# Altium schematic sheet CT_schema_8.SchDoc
size 278 x 170 mm
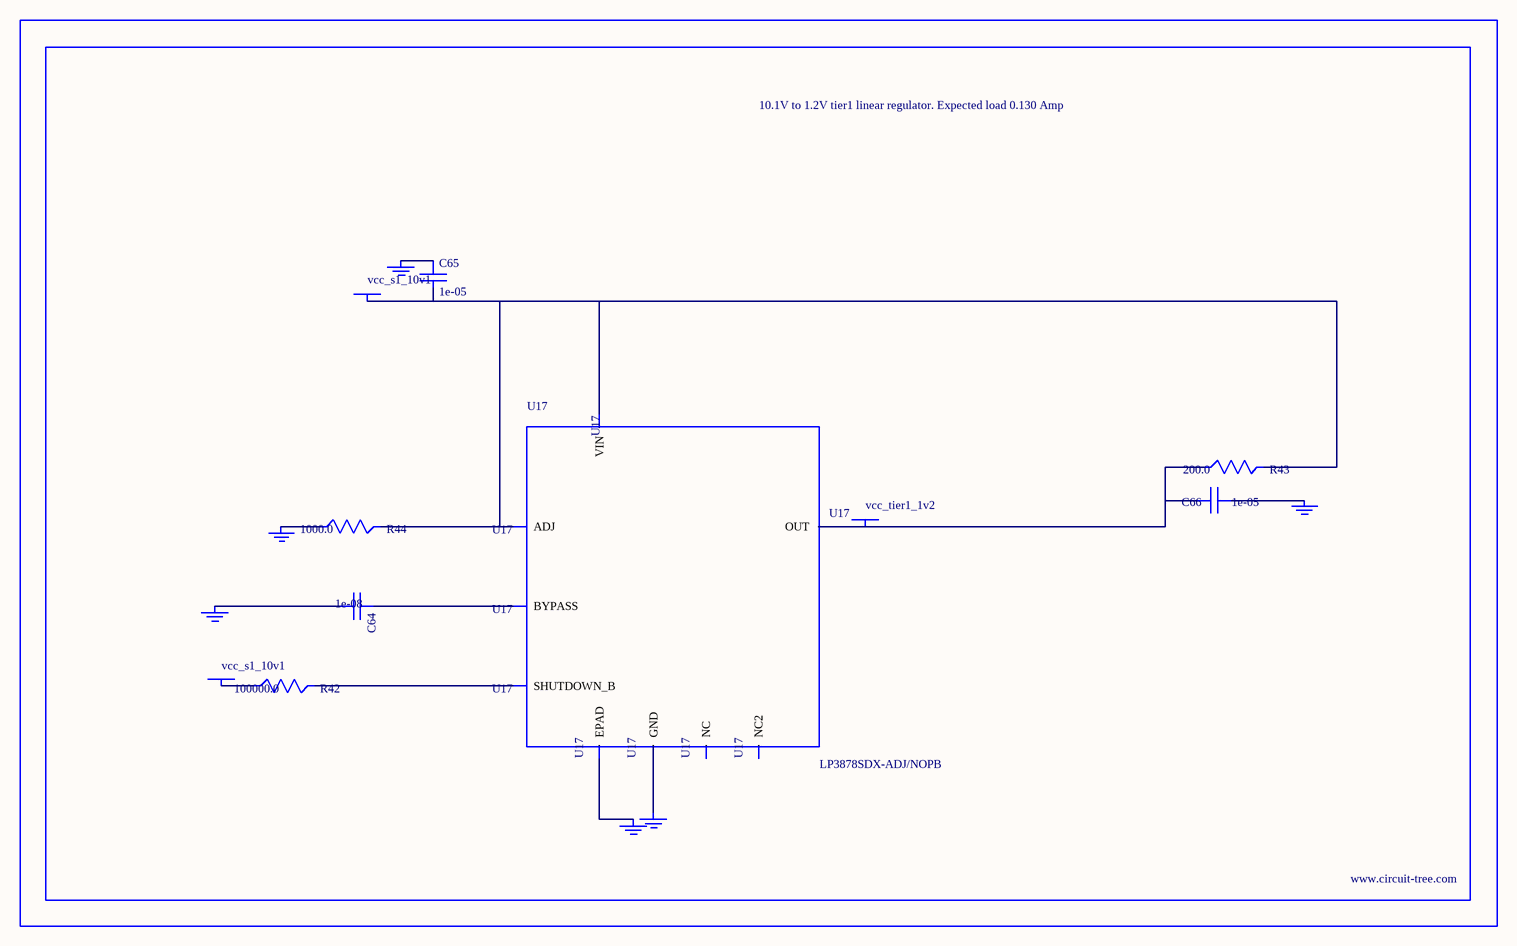
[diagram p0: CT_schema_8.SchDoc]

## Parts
BORDER7  (no value)
C64  1e-08  [C0402]
C65  1e-05  [C1206]
C66  1e-05  [C0805]
GND_INSTANCE_7_0  (no value)
GND_INSTANCE_7_1  (no value)
GND_INSTANCE_7_2  (no value)
GND_INSTANCE_7_3  (no value)
GND_INSTANCE_7_4  (no value)
GND_INSTANCE_7_5  (no value)
POWER_INSTANCE_7_0  vcc_s1_10v1
POWER_INSTANCE_7_1  vcc_s1_10v1
POWER_INSTANCE_7_2  vcc_tier1_1v2
R42  100000.0  [R0603]
R43  200.0  [R0603]
R44  1000.0  [R0603]
U17  LP3878SDX-ADJ/NOPB  [WSON-8]

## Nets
NetC64_1: C64.1 U17.1(BYPASS)
NetC64_2: C64.2 GND_INSTANCE_7_0.0(GND)
NetC65_1: C65.1 GND_INSTANCE_7_1.0(GND)
NetC65_2: C65.2 POWER_INSTANCE_7_0.0(PWR) R43.2 R44.2 U17.4(VIN) U17.6(ADJ)
NetC66_1: C66.1 GND_INSTANCE_7_2.0(GND)
NetC66_2: C66.2 POWER_INSTANCE_7_2.0(PWR) R43.1 U17.5(OUT)
NetGND_INSTANCE_7_3_0: GND_INSTANCE_7_3.0(GND) R44.1
NetGND_INSTANCE_7_4_0: GND_INSTANCE_7_4.0(GND) U17.PAD(EPAD)
NetGND_INSTANCE_7_5_0: GND_INSTANCE_7_5.0(GND) U17.3(GND)
NetPOWER_INSTANCE_7_1_0: POWER_INSTANCE_7_1.0(PWR) R42.1
NetR42_2: R42.2 U17.8(SHUTDOWN_B)

Not connected (* = marked no-connect by the designer): U17 2(NC) 7(NC2)

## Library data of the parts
BORDER7 = BORDER_PAGE7
C64 = C0402C103K3RAC
C65 = C1206C106K3RACTU
C66 = GRM219R60J106ME19D
GND_INSTANCE_7_0-GND_INSTANCE_7_5 = GND
POWER_INSTANCE_7_0-POWER_INSTANCE_7_2 = PWR
R42 = RC0603JR-07100KL
R43 = RC0603JR-07200RL
R44 = RC0603JR-071KL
